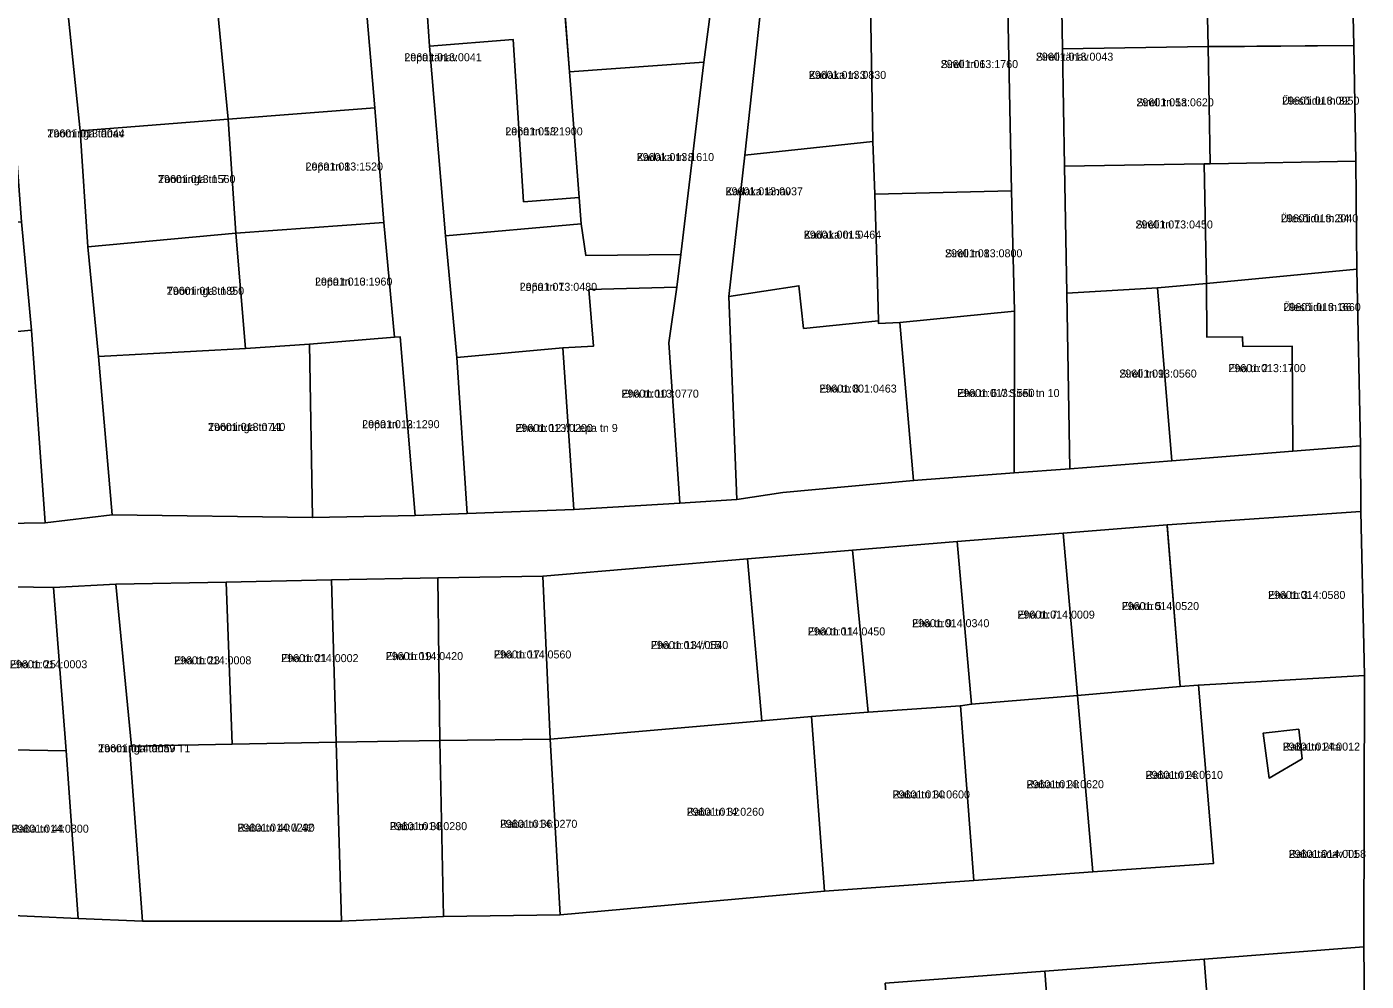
# Model space of a CAD drawing. Extents: x 518839 to 525192, y 6573164 to 6576561.
# Drawn here: x 523988.3 to 524239.3, y 6573652.7 to 6573831.7 of the extents above; entities that cross this region are included whole.
import ezdxf

# ---------------------------------------------------------------- set-up
doc = ezdxf.new("R2010")
doc.units = 0
for name, color, linetype in [('L_AADRESS', 7, 'Continuous'), ('PIIR', 7, 'Continuous'), ('TUNNUS', 7, 'Continuous')]:
    doc.layers.add(name, color=color, linetype=linetype)

msp = doc.modelspace()

# ---------------------------------------------------------------- linework, layer by layer
at = {"layer": 'PIIR'}
for points in [[(524239.31, 6573619.05), (524238.88, 6573659.13), (524239.02, 6573710.03), (524238.3, 6573740.81), (524238.21, 6573753.11), (524237.58, 6573786.23), (524237.36, 6573806.47), (524236.99, 6573828.15), (524236.46, 6573850.03), (524236.22, 6573874.23), (524235.66, 6573907.19), (524235.43, 6573919.25), (524235.19, 6573950.42), (524234.03, 6573985.67), (524230.53, 6574045.11)], [(523955.98, 6573738.09), (523991.73, 6573738.64), (524004.3, 6573740.13), (524041.83, 6573739.66), (524061.06, 6573740.01), (524070.8, 6573740.41), (524090.83, 6573741.16), (524110.68, 6573742.36), (524121.33, 6573743.05), (524129.99, 6573744.34), (524154.47, 6573746.58), (524173.3, 6573748.03), (524183.79, 6573748.78), (524202.85, 6573750.27), (524225.55, 6573752.07), (524238.21, 6573753.11), (524238.3, 6573740.81), (524202.01, 6573738.27), (524182.53, 6573736.72), (524162.67, 6573735.18), (524143.01, 6573733.53), (524123.35, 6573731.88), (524085.01, 6573728.68), (524065.29, 6573728.32), (524045.37, 6573727.96), (524025.66, 6573727.52), (524004.95, 6573727.13), (523993.31, 6573726.55), (523974.58, 6573726.83)], [(523973.3, 6573665.56), (523997.88, 6573664.48), (524009.98, 6573663.97), (524047.25, 6573663.94), (524066.37, 6573664.82), (524088.22, 6573665.12), (524137.78, 6573669.59), (524165.74, 6573671.59), (524188.05, 6573673.19), (524210.7, 6573674.8), (524207.85, 6573708.23), (524239.02, 6573710.03), (524238.88, 6573659.13), (524208.97, 6573656.86), (524179.05, 6573654.59), (524149.14, 6573652.32)]]:
    msp.add_lwpolyline(points, dxfattribs=at)
for points in [[(524171.01, 6573901.81), (524181.14, 6573902.62), (524181.69, 6573869.65), (524182.03, 6573849.5), (524182.4, 6573827.52), (524182.77, 6573805.55), (524183.22, 6573781.74), (524183.79, 6573748.78), (524173.3, 6573748.03), (524173.42, 6573778.34), (524172.85, 6573800.9), (524171.9, 6573847.55), (524171.54, 6573871.84)], [(524118.3, 6573897.21), (524127.26, 6573898.06), (524129.88, 6573868.3), (524125.71, 6573834.07), (524122.82, 6573807.59), (524119.88, 6573781.09), (524121.33, 6573743.05), (524110.68, 6573742.36), (524108.59, 6573772.41), (524110.09, 6573782.88), (524110.84, 6573788.98), (524115.19, 6573825.02), (524118.19, 6573847.87), (524120.39, 6573867.6)], [(524047.28, 6573890.84), (524058.55, 6573892.23), (524061.06, 6573862.34), (524063.01, 6573839.09), (524063.75, 6573828.06), (524066.74, 6573792.48), (524068.87, 6573769.65), (524070.8, 6573740.41), (524061.06, 6573740.01), (524058.24, 6573773.57), (524057.22, 6573773.49), (524055.17, 6573794.96), (524053.5, 6573816.5), (524049.82, 6573859.68)], [(523979.96, 6573886.04), (523991.91, 6573886.74), (523993.87, 6573855.18), (523998.29, 6573812.14), (523999.71, 6573790.43), (524001.71, 6573769.87), (524004.3, 6573740.13), (523991.73, 6573738.64), (523989.14, 6573774.8), (523987.31, 6573795.12), (523985.77, 6573815.38), (523983.8, 6573835.68), (523982.65, 6573856.32)], [(524021.85, 6573857.47), (524049.82, 6573859.68), (524053.5, 6573816.5), (524025.99, 6573814.33)], [(523993.87, 6573855.18), (524013.16, 6573856.78), (524021.85, 6573857.47), (524025.99, 6573814.33), (523998.29, 6573812.14)], [(524182.03, 6573849.5), (524209.16, 6573849.98), (524209.7, 6573827.98), (524182.4, 6573827.52)], [(524209.16, 6573849.98), (524210.49, 6573849.92), (524236.46, 6573850.03), (524236.99, 6573828.15), (524209.69, 6573827.93)], [(524115.19, 6573825.02), (524089.98, 6573823.21), (524088.29, 6573845.35), (524118.19, 6573847.87)], [(524146.27, 6573847), (524171.9, 6573847.55), (524172.85, 6573800.9), (524147.23, 6573800.32), (524146.85, 6573810.16), (524146.43, 6573836.06)], [(524063.01, 6573839.09), (524088.56, 6573841.38), (524089.98, 6573823.21), (524091.79, 6573799.67), (524081.38, 6573798.86), (524079.42, 6573829.3), (524063.75, 6573828.06)], [(524125.71, 6573834.07), (524146.43, 6573836.06), (524146.85, 6573810.16), (524122.82, 6573807.59)], [(524063.75, 6573828.06), (524079.42, 6573829.3), (524081.38, 6573798.86), (524091.79, 6573799.67), (524092.17, 6573794.7), (524066.74, 6573792.48)], [(524182.4, 6573827.52), (524209.7, 6573827.98), (524210.07, 6573806.01), (524208.93, 6573805.99), (524182.77, 6573805.55)], [(524236.99, 6573828.15), (524237.36, 6573806.47), (524210.07, 6573806.01), (524209.7, 6573827.98)], [(524115.19, 6573825.02), (524110.84, 6573788.98), (524093.07, 6573788.77), (524092.17, 6573794.7), (524091.79, 6573799.67), (524089.98, 6573823.21)], [(524025.99, 6573814.33), (524053.5, 6573816.5), (524055.17, 6573794.96), (524027.47, 6573792.96)], [(523998.29, 6573812.14), (524025.99, 6573814.33), (524027.47, 6573792.96), (523999.71, 6573790.43)], [(524119.88, 6573781.09), (524122.82, 6573807.59), (524146.85, 6573810.16), (524147.23, 6573800.32), (524147.7, 6573783.76), (524147.92, 6573776.53), (524133.85, 6573775.12), (524132.99, 6573783.12)], [(524182.77, 6573805.55), (524208.93, 6573805.99), (524209.35, 6573783.57), (524200.19, 6573782.71), (524183.22, 6573781.74)], [(524208.93, 6573805.99), (524210.07, 6573806.01), (524237.36, 6573806.47), (524237.58, 6573786.23), (524209.35, 6573783.57)], [(524147.92, 6573776.53), (524147.7, 6573783.76), (524147.23, 6573800.32), (524172.85, 6573800.9), (524173.42, 6573778.34), (524151.91, 6573776.22), (524147.92, 6573776.01)], [(523958.25, 6573792.38), (523987.31, 6573795.12), (523989.14, 6573774.8), (523959.83, 6573772.02)], [(524029.25, 6573771.33), (524027.47, 6573792.96), (524055.17, 6573794.96), (524057.22, 6573773.49), (524041.23, 6573772.15)], [(524066.74, 6573792.48), (524092.17, 6573794.7), (524093.07, 6573788.77), (524110.84, 6573788.98), (524110.09, 6573782.88), (524093.6, 6573782.4), (524094.49, 6573771.8), (524088.76, 6573771.47), (524068.87, 6573769.65)], [(523999.71, 6573790.43), (524027.47, 6573792.96), (524029.25, 6573771.33), (524001.71, 6573769.87)], [(524216.14, 6573773.51), (524209.44, 6573773.45), (524209.35, 6573783.57), (524237.58, 6573786.23), (524238.21, 6573753.11), (524225.55, 6573752.07), (524225.42, 6573771.82), (524216.16, 6573771.74)], [(524121.33, 6573743.05), (524119.88, 6573781.09), (524132.99, 6573783.12), (524133.85, 6573775.12), (524147.92, 6573776.53), (524147.92, 6573776.01), (524151.91, 6573776.22), (524154.47, 6573746.58), (524129.99, 6573744.34)], [(524200.19, 6573782.71), (524209.35, 6573783.57), (524209.44, 6573773.45), (524216.14, 6573773.51), (524216.16, 6573771.74), (524225.42, 6573771.82), (524225.55, 6573752.07), (524202.85, 6573750.27)], [(524088.76, 6573771.47), (524094.49, 6573771.8), (524093.6, 6573782.4), (524110.09, 6573782.88), (524108.59, 6573772.41), (524110.68, 6573742.36), (524090.83, 6573741.16)], [(524200.19, 6573782.71), (524202.85, 6573750.27), (524183.79, 6573748.78), (524183.22, 6573781.74)], [(524151.91, 6573776.22), (524173.42, 6573778.34), (524173.3, 6573748.03), (524154.47, 6573746.58)], [(523991.73, 6573738.64), (523955.98, 6573738.09), (523955.88, 6573771.65), (523959.83, 6573772.02), (523989.14, 6573774.8)], [(524041.23, 6573772.15), (524057.22, 6573773.49), (524058.24, 6573773.57), (524061.06, 6573740.01), (524041.83, 6573739.66)], [(524001.71, 6573769.87), (524029.25, 6573771.33), (524041.23, 6573772.15), (524041.83, 6573739.66), (524004.3, 6573740.13)], [(524068.87, 6573769.65), (524088.76, 6573771.47), (524090.83, 6573741.16), (524070.8, 6573740.41)], [(524204.44, 6573707.97), (524202.02, 6573738.09), (524202.01, 6573738.27), (524238.3, 6573740.81), (524239.02, 6573710.03), (524207.85, 6573708.23)], [(524202.01, 6573738.27), (524204.44, 6573707.97), (524185.21, 6573706.29), (524182.53, 6573736.72)], [(524182.53, 6573736.72), (524185.21, 6573706.29), (524165.36, 6573704.64), (524162.67, 6573735.18)], [(524123.35, 6573731.88), (524143.01, 6573733.53), (524145.96, 6573703.15), (524135.33, 6573702.34), (524126.05, 6573701.53)], [(524143.01, 6573733.53), (524162.67, 6573735.18), (524165.36, 6573704.64), (524163.25, 6573704.35), (524145.96, 6573703.15)], [(524086.37, 6573698.09), (524085.01, 6573728.68), (524123.35, 6573731.88), (524126.05, 6573701.53)], [(524025.66, 6573727.52), (524045.37, 6573727.96), (524046.24, 6573697.56), (524026.76, 6573697.13)], [(524045.37, 6573727.96), (524065.29, 6573728.32), (524065.7, 6573697.83), (524046.24, 6573697.56)], [(524065.29, 6573728.32), (524085.01, 6573728.68), (524086.37, 6573698.09), (524065.7, 6573697.83)], [(523974.58, 6573726.83), (523993.31, 6573726.55), (523995.65, 6573695.93), (523975.03, 6573696.27)], [(523993.31, 6573726.55), (524004.95, 6573727.13), (524007.93, 6573696.79), (524007.5, 6573696.78), (524009.98, 6573663.97), (523997.88, 6573664.48), (523995.65, 6573695.93)], [(524025.66, 6573727.52), (524026.76, 6573697.13), (524007.93, 6573696.79), (524004.95, 6573727.13)], [(524185.21, 6573706.29), (524204.44, 6573707.97), (524207.85, 6573708.23), (524210.7, 6573674.8), (524188.05, 6573673.19)], [(524165.74, 6573671.59), (524163.25, 6573704.35), (524165.36, 6573704.64), (524185.21, 6573706.29), (524188.05, 6573673.19)], [(524137.78, 6573669.59), (524135.33, 6573702.34), (524145.96, 6573703.15), (524163.25, 6573704.35), (524165.74, 6573671.59)], [(524086.37, 6573698.09), (524126.05, 6573701.53), (524135.33, 6573702.34), (524137.78, 6573669.59), (524088.22, 6573665.12)], [(524046.24, 6573697.56), (524065.7, 6573697.83), (524066.37, 6573664.82), (524047.25, 6573663.94)], [(524065.7, 6573697.83), (524086.37, 6573698.09), (524088.22, 6573665.12), (524066.37, 6573664.82)], [(524227.3, 6573694.41), (524221.12, 6573690.81), (524220, 6573699.22), (524226.67, 6573699.94)], [(524220, 6573699.22), (524221.12, 6573690.81), (524227.3, 6573694.41), (524226.67, 6573699.94)], [(523972.87, 6573696.12), (523975.03, 6573696.27), (523995.65, 6573695.93), (523997.88, 6573664.48), (523973.3, 6573665.56)], [(524046.24, 6573697.56), (524047.25, 6573663.94), (524009.98, 6573663.97), (524007.5, 6573696.78), (524007.93, 6573696.79), (524026.76, 6573697.13)], [(524208.97, 6573656.86), (524238.88, 6573659.13), (524239.31, 6573619.05), (524211.99, 6573616.98)], [(524179.05, 6573654.59), (524208.97, 6573656.86), (524211.99, 6573616.98), (524182.07, 6573614.71)], [(524149.14, 6573652.32), (524179.05, 6573654.59), (524182.07, 6573614.71), (524152.16, 6573612.44)]]:
    msp.add_lwpolyline(points, close=True, dxfattribs=at)

# ---------------------------------------------------------------- texts
at = {"layer": 'L_AADRESS'}
for s, p in [('Lepa tänav', (524059.04, 6573825.22)), ('Sireli tänav', (524177.4, 6573825.32)), ('Kadaka tn 3', (524134.84, 6573821.91)), ('Sireli tn 6', (524159.56, 6573823.94)), ('Sireli tn 5a', (524196.24, 6573816.77)), ('Ülesõidu tn 32', (524223.53, 6573817.08)), ('Toominga tänav', (523992.13, 6573810.94)), ('Lepa tn 5/2', (524077.96, 6573811.32)), ('Lepa tn 8', (524040.53, 6573804.73)), ('Kadaka tn 8', (524102.58, 6573806.5)), ('Toominga tn 7', (524012.87, 6573802.38)), ('Kadaka tänav', (524119.24, 6573800.08)), ('Ülesõidu tn 34', (524223.31, 6573795.02)), ('Kadaka tn 5', (524133.9, 6573791.95)), ('Sireli tn 7', (524196.07, 6573793.86)), ('Sireli tn 8', (524160.37, 6573788.46)), ('Lepa tn 10', (524042.29, 6573783.15)), ('Lepa tn 7', (524080.66, 6573782.17)), ('Toominga tn 9', (524014.5, 6573781.42)), ('Ülesõidu tn 36', (524223.78, 6573778.37)), ('Eha tn 2', (524213.47, 6573766.92)), ('Sireli tn 9', (524193.04, 6573765.9)), ('Eha tn 10', (524099.72, 6573762.14)), ('Eha tn 8', (524136.81, 6573763.09)), ('Eha tn 6 // Sireli tn 10', (524162.66, 6573762.25)), ('Lepa tn 12', (524051.14, 6573756.41)), ('Toominga tn 11', (524022.23, 6573755.9)), ('Eha tn 12 // Lepa tn 9', (524079.85, 6573755.7)), ('Eha tn 3', (524220.9, 6573724.39)), ('Eha tn 5', (524193.48, 6573722.3)), ('Eha tn 9', (524154.18, 6573719.09)), ('Eha tn 7', (524173.94, 6573720.7)), ('Eha tn 11', (524134.66, 6573717.55)), ('Eha tn 13 // 15', (524105.24, 6573714.99)), ('Eha tn 25', (523985.11, 6573711.39)), ('Eha tn 23', (524015.86, 6573712.13)), ('Eha tn 21', (524035.95, 6573712.54)), ('Eha tn 19', (524055.54, 6573712.92)), ('Eha tn 17', (524075.83, 6573713.23)), ('Toominga tänav T1', (524001.64, 6573695.64)), ('Raba tn 24a', (524223.65, 6573695.95)), ('Raba tn 28', (524175.65, 6573688.9)), ('Raba tn 26', (524197.96, 6573690.65)), ('Raba tn 30', (524150.54, 6573686.98)), ('Raba tn 32', (524111.95, 6573683.73)), ('Raba tn 38', (524056.3, 6573681.03)), ('Raba tn 36', (524076.96, 6573681.47)), ('Raba tn 44', (523985.38, 6573680.56)), ('Raba tn 40 // 42', (524027.73, 6573680.75)), ('Raba tänav T1', (524224.77, 6573675.83))]:
    msp.add_text(s, height=1.5, dxfattribs=at).set_placement(p)
at = {"layer": 'TUNNUS'}
for s, p in [('29601:013:0041', (524059.04, 6573825.22)), ('29601:013:0043', (524177.4, 6573825.32)), ('29601:013:0830', (524134.84, 6573821.91)), ('29601:013:1760', (524159.56, 6573823.94)), ('29601:013:0620', (524196.24, 6573816.77)), ('29601:013:0950', (524223.53, 6573817.08)), ('29601:013:0044', (523992.13, 6573810.94)), ('29601:013:1900', (524077.96, 6573811.32)), ('29601:013:1520', (524040.53, 6573804.73)), ('29601:013:1610', (524102.58, 6573806.5)), ('29601:013:1560', (524012.87, 6573802.38)), ('29601:013:0037', (524119.24, 6573800.08)), ('29601:013:2040', (524223.31, 6573795.02)), ('29601:001:0464', (524133.9, 6573791.95)), ('29601:013:0450', (524196.07, 6573793.86)), ('29601:013:0800', (524160.37, 6573788.46)), ('29601:013:1960', (524042.29, 6573783.15)), ('29601:013:0480', (524080.66, 6573782.17)), ('29601:013:1850', (524014.5, 6573781.42)), ('29601:013:1660', (524223.78, 6573778.37)), ('29601:013:1700', (524213.47, 6573766.92)), ('29601:013:0560', (524193.04, 6573765.9)), ('29601:013:0770', (524099.72, 6573762.14)), ('29601:001:0463', (524136.81, 6573763.09)), ('29601:013:1550', (524162.66, 6573762.25)), ('29601:013:1290', (524051.14, 6573756.41)), ('29601:013:0740', (524022.23, 6573755.9)), ('29601:013:0200', (524079.85, 6573755.7)), ('29601:014:0580', (524220.9, 6573724.39)), ('29601:014:0520', (524193.48, 6573722.3)), ('29601:014:0340', (524154.18, 6573719.09)), ('29601:014:0009', (524173.94, 6573720.7)), ('29601:014:0450', (524134.66, 6573717.55)), ('29601:014:0540', (524105.24, 6573714.99)), ('29601:014:0003', (523985.11, 6573711.39)), ('29601:014:0008', (524015.86, 6573712.13)), ('29601:014:0002', (524035.95, 6573712.54)), ('29601:014:0420', (524055.54, 6573712.92)), ('29601:014:0560', (524075.83, 6573713.23)), ('29601:014:0059', (524001.64, 6573695.64)), ('29601:014:0012', (524223.65, 6573695.95)), ('29601:014:0620', (524175.65, 6573688.9)), ('29601:014:0610', (524197.96, 6573690.65)), ('29601:014:0600', (524150.54, 6573686.98)), ('29601:014:0260', (524111.95, 6573683.73)), ('29601:014:0270', (524076.96, 6573681.47)), ('29601:014:0300', (523985.38, 6573680.56)), ('29601:014:0290', (524027.73, 6573680.75)), ('29601:014:0280', (524056.3, 6573681.03)), ('29601:014:0058', (524224.77, 6573675.83))]:
    msp.add_text(s, height=1.5, dxfattribs=at).set_placement(p)

doc.saveas('drawing.dxf')
